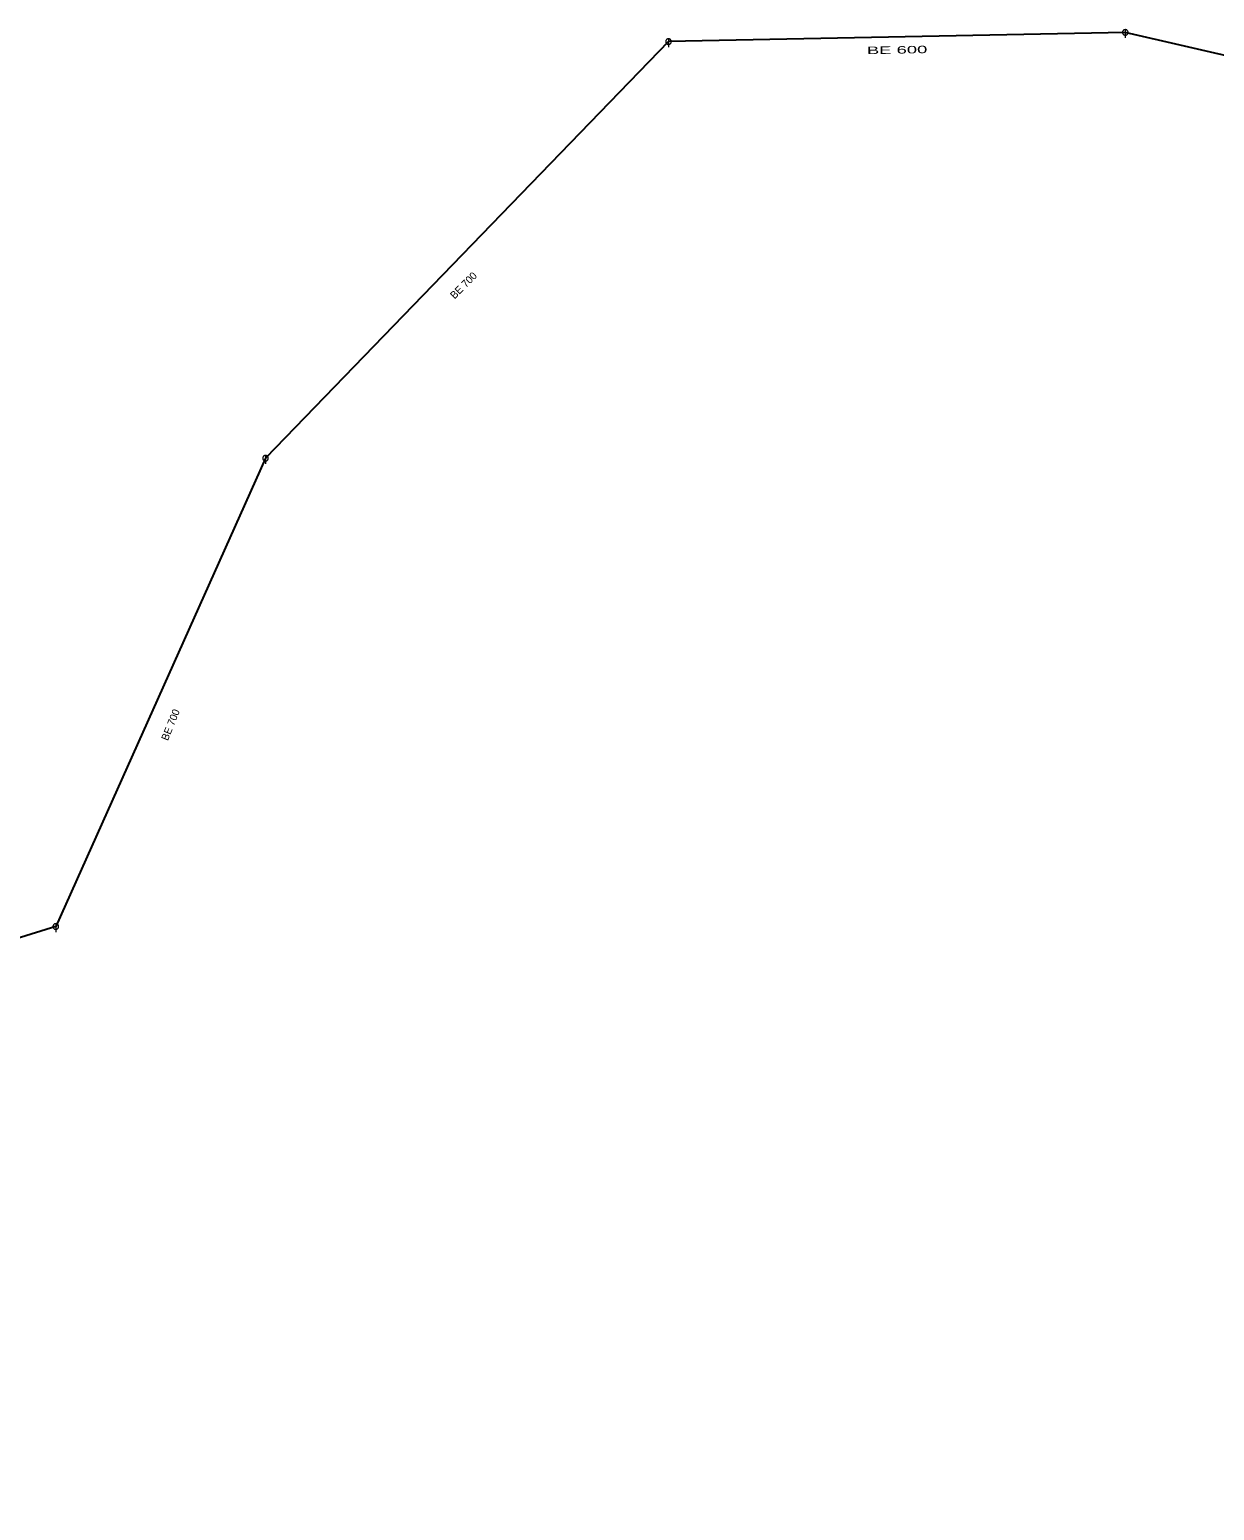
# Model space of a CAD drawing. Extents: x -687515 to -686506, y -974029 to -973461.
# Drawn here: x -686858.1 to -686751.9, y -974015.7 to -973883 of the extents above; entities that cross this region are included whole.
import ezdxf
from ezdxf.enums import TextEntityAlignment as Align

# ---------------------------------------------------------------- set-up
doc = ezdxf.new("R2010")
doc.units = 0
doc.header["$LTSCALE"] = 0.27
for name, color, linetype, lineweight in [('1', 7, 'Continuous', 13), ('14', 7, 'Continuous', 25), ('22', 7, 'Continuous', 13)]:
    doc.layers.add(name, color=color, linetype=linetype, lineweight=lineweight)

msp = doc.modelspace()

# ---------------------------------------------------------------- linework, layer by layer
at = {"layer": '14'}
for p, q in [((-686800.831, -973884.042), (-686836.948, -973921.392)), ((-686759.899, -973883.22), (-686800.832, -973884.042)), ((-686710.057, -973894.737), (-686759.899, -973883.22)), ((-686836.948, -973921.392), (-686855.743, -973963.372))]:
    msp.add_line(p, q, dxfattribs=at)
msp.add_lwpolyline([(-686855.743, -973963.372), (-686930.422, -973986.59), (-686994.885, -974015.71)], dxfattribs=at)
at = {"layer": '22'}
for p, q in [((-686800.831, -973883.79), (-686800.832, -973884.534)), ((-686759.898, -973882.968), (-686759.899, -973883.712)), ((-686836.947, -973921.14), (-686836.948, -973921.884)), ((-686855.742, -973963.12), (-686855.743, -973963.864))]:
    msp.add_line(p, q, dxfattribs=at)
for points in [[(-686800.58, -973884.042), (-686800.581, -973884.016), (-686800.585, -973883.99), (-686800.591, -973883.964), (-686800.601, -973883.94), (-686800.613, -973883.916), (-686800.627, -973883.894), (-686800.644, -973883.873), (-686800.662, -973883.855), (-686800.683, -973883.838), (-686800.705, -973883.824), (-686800.729, -973883.812), (-686800.753, -973883.802), (-686800.779, -973883.796), (-686800.805, -973883.792), (-686800.831, -973883.79), (-686800.857, -973883.791), (-686800.883, -973883.795), (-686800.909, -973883.801), (-686800.934, -973883.811), (-686800.957, -973883.823), (-686800.979, -973883.837), (-686801, -973883.854), (-686801.018, -973883.872), (-686801.035, -973883.893), (-686801.049, -973883.915), (-686801.061, -973883.939), (-686801.071, -973883.963), (-686801.078, -973883.989), (-686801.082, -973884.015), (-686801.084, -973884.041), (-686801.083, -973884.067), (-686801.079, -973884.093), (-686801.072, -973884.119), (-686801.062, -973884.144), (-686801.05, -973884.167), (-686801.036, -973884.189), (-686801.019, -973884.21), (-686801.001, -973884.228), (-686800.98, -973884.245), (-686800.958, -973884.259), (-686800.935, -973884.271), (-686800.91, -973884.281), (-686800.884, -973884.288), (-686800.858, -973884.292), (-686800.832, -973884.294), (-686800.806, -973884.293), (-686800.78, -973884.289), (-686800.754, -973884.282), (-686800.73, -973884.272), (-686800.706, -973884.26), (-686800.684, -973884.246), (-686800.663, -973884.229), (-686800.645, -973884.211), (-686800.628, -973884.19), (-686800.614, -973884.168), (-686800.602, -973884.145), (-686800.592, -973884.12), (-686800.586, -973884.094), (-686800.582, -973884.068)], [(-686759.647, -973883.22), (-686759.648, -973883.194), (-686759.652, -973883.168), (-686759.658, -973883.142), (-686759.668, -973883.118), (-686759.68, -973883.094), (-686759.694, -973883.072), (-686759.711, -973883.051), (-686759.729, -973883.033), (-686759.75, -973883.016), (-686759.772, -973883.002), (-686759.796, -973882.99), (-686759.82, -973882.98), (-686759.846, -973882.974), (-686759.872, -973882.97), (-686759.898, -973882.968), (-686759.924, -973882.969), (-686759.95, -973882.973), (-686759.976, -973882.979), (-686760.001, -973882.989), (-686760.024, -973883.001), (-686760.046, -973883.015), (-686760.067, -973883.032), (-686760.085, -973883.05), (-686760.102, -973883.071), (-686760.116, -973883.093), (-686760.128, -973883.117), (-686760.138, -973883.141), (-686760.145, -973883.167), (-686760.149, -973883.193), (-686760.151, -973883.219), (-686760.15, -973883.245), (-686760.146, -973883.271), (-686760.139, -973883.297), (-686760.129, -973883.322), (-686760.117, -973883.345), (-686760.103, -973883.367), (-686760.086, -973883.388), (-686760.068, -973883.406), (-686760.047, -973883.423), (-686760.025, -973883.437), (-686760.002, -973883.449), (-686759.977, -973883.459), (-686759.951, -973883.466), (-686759.925, -973883.47), (-686759.899, -973883.472), (-686759.873, -973883.471), (-686759.847, -973883.467), (-686759.821, -973883.46), (-686759.797, -973883.45), (-686759.773, -973883.438), (-686759.751, -973883.424), (-686759.73, -973883.407), (-686759.712, -973883.389), (-686759.695, -973883.368), (-686759.681, -973883.346), (-686759.669, -973883.323), (-686759.659, -973883.298), (-686759.653, -973883.272), (-686759.649, -973883.246)], [(-686836.696, -973921.392), (-686836.697, -973921.366), (-686836.701, -973921.34), (-686836.707, -973921.314), (-686836.717, -973921.29), (-686836.729, -973921.266), (-686836.743, -973921.244), (-686836.76, -973921.223), (-686836.778, -973921.205), (-686836.799, -973921.188), (-686836.821, -973921.174), (-686836.845, -973921.162), (-686836.869, -973921.152), (-686836.895, -973921.146), (-686836.921, -973921.142), (-686836.947, -973921.14), (-686836.973, -973921.141), (-686836.999, -973921.145), (-686837.025, -973921.151), (-686837.05, -973921.161), (-686837.073, -973921.173), (-686837.095, -973921.187), (-686837.116, -973921.204), (-686837.134, -973921.222), (-686837.151, -973921.243), (-686837.165, -973921.265), (-686837.177, -973921.289), (-686837.187, -973921.313), (-686837.194, -973921.339), (-686837.198, -973921.365), (-686837.2, -973921.391), (-686837.199, -973921.417), (-686837.195, -973921.443), (-686837.188, -973921.469), (-686837.178, -973921.494), (-686837.166, -973921.517), (-686837.152, -973921.539), (-686837.135, -973921.56), (-686837.117, -973921.578), (-686837.096, -973921.595), (-686837.074, -973921.609), (-686837.051, -973921.621), (-686837.026, -973921.631), (-686837, -973921.638), (-686836.974, -973921.642), (-686836.948, -973921.644), (-686836.922, -973921.643), (-686836.896, -973921.639), (-686836.87, -973921.632), (-686836.846, -973921.622), (-686836.822, -973921.61), (-686836.8, -973921.596), (-686836.779, -973921.579), (-686836.761, -973921.561), (-686836.744, -973921.54), (-686836.73, -973921.518), (-686836.718, -973921.495), (-686836.708, -973921.47), (-686836.702, -973921.444), (-686836.698, -973921.418)], [(-686855.491, -973963.372), (-686855.492, -973963.346), (-686855.496, -973963.32), (-686855.502, -973963.294), (-686855.512, -973963.27), (-686855.524, -973963.246), (-686855.538, -973963.224), (-686855.555, -973963.203), (-686855.573, -973963.185), (-686855.594, -973963.168), (-686855.616, -973963.154), (-686855.64, -973963.142), (-686855.664, -973963.132), (-686855.69, -973963.126), (-686855.716, -973963.122), (-686855.742, -973963.12), (-686855.768, -973963.121), (-686855.794, -973963.125), (-686855.82, -973963.131), (-686855.845, -973963.141), (-686855.868, -973963.153), (-686855.89, -973963.167), (-686855.911, -973963.184), (-686855.929, -973963.202), (-686855.946, -973963.223), (-686855.96, -973963.245), (-686855.972, -973963.269), (-686855.982, -973963.293), (-686855.989, -973963.319), (-686855.993, -973963.345), (-686855.995, -973963.371), (-686855.994, -973963.397), (-686855.99, -973963.423), (-686855.983, -973963.449), (-686855.973, -973963.474), (-686855.961, -973963.497), (-686855.947, -973963.519), (-686855.93, -973963.54), (-686855.912, -973963.558), (-686855.891, -973963.575), (-686855.869, -973963.589), (-686855.846, -973963.601), (-686855.821, -973963.611), (-686855.795, -973963.618), (-686855.769, -973963.622), (-686855.743, -973963.624), (-686855.717, -973963.623), (-686855.691, -973963.619), (-686855.665, -973963.612), (-686855.641, -973963.602), (-686855.617, -973963.59), (-686855.595, -973963.576), (-686855.574, -973963.559), (-686855.556, -973963.541), (-686855.539, -973963.52), (-686855.525, -973963.498), (-686855.513, -973963.475), (-686855.503, -973963.45), (-686855.497, -973963.424), (-686855.493, -973963.398)]]:
    msp.add_lwpolyline(points, close=True, dxfattribs=at)

# ---------------------------------------------------------------- texts
at = {"layer": '1', "width": 1.85}
msp.add_text('BE 600', height=0.6667, rotation=1, dxfattribs=at).set_placement((-686780.34, -973885.121), align=Align.CENTER)
at = {"layer": '1'}
for rotation, p in [(45, (-686818.968, -973906.132)), (68, (-686845.151, -973945.41))]:
    msp.add_text('BE 700', height=0.6667, rotation=rotation, dxfattribs=at).set_placement(p, align=Align.CENTER)

doc.saveas('drawing.dxf')
